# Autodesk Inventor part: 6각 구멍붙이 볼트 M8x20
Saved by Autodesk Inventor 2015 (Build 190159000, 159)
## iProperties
Created: 2025-06
Part Number: 6각 구멍붙이 볼트 M8x20
Material: 일반
Document SubType Name: Modeling
Designer: 104
Density: 1 g/cm^3
Appearance: 기본값
Author: 104
Author: jhkim
Description: 6각머리 태핑 나사
Creation Date: 2025-06-19
Sending System: Autodesk Inventor 2026
Preprocessor: ST-DEVELOPER v20.1
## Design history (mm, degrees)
node "6각 구멍붙이 볼트 M8x201"
body "Solid1"
node "기준1"
